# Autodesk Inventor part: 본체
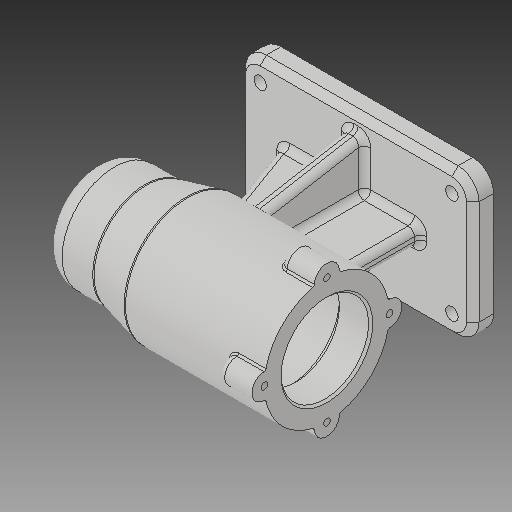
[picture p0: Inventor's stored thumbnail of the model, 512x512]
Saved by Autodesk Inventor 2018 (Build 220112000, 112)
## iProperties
Created: 2019-07
Part Number: 본체
Material: 일반
Document SubType Name: Modeling
Designer: USER
Density: 1 g/cm^3
Appearance: 기본값
Author: USER
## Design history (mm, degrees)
sketch "스케치1"
  geometry: L1 (0, 70)-(112, 70); L2 (112, 70)-(112, 0); L3 (112, 0)-(0, 0); L4 (0, 0)-(0, 70); 1 further point
  constraints: 8 end point, 2 parallel, 1 coincident, 1 horizontal, 1 perpendicular
  dimensions: "d0" = 112 distance of L1.start L1.end; "d1" = 70 distance of L3.end L1.start
extrude "돌출1" new body sketch "스케치1" distance "d2" = 10; taper "d3" = 0 deg
node "작업 평면1"
sketch "스케치2"
  geometry: L1 (0, 80)-(112, 80); L2 (112, 10)-(0, 10) reference; L3 (0, 0)-(112, 0) reference; L4 (0, 80)-(0, 105); L5 (0, 105)-(25, 105); L6 (25, 105)-(45, 110); L7 (45, 110)-(112, 110); L8 (112, 80)-(112, 110); L9 (112, 101)-(97, 101); L10 (97, 101)-(97, 104); L11 (97, 104)-(43, 104); L12 (43, 104)-(43, 101); L13 (43, 101)-(31, 101); L14 (31, 101)-(31, 97.5); L15 (31, 97.5)-(13, 97.5); L16 (13, 97.5)-(13, 96); L17 (13, 96)-(9, 96); L18 (9, 96)-(9, 90.5); L19 (9, 90.5)-(6, 90.5); L20 (6, 90.5)-(6, 80); L21 (0, 80)-(112, 80); 2 further points
  constraints: 38 end point, 11 perpendicular, 5 horizontal, 2 midpoint, 2 point on line, 2 vertical, 1 vertical alignment
  dimensions: "d4" = 112 distance of L1.start L1.end; "d5" = 80 distance between parallel lines of L3 L1; "d6" = 60 diameter of L7 L1; "d7" = 50 diameter of L5 L1; "d8" = 25 distance of L4.end L5.end; "d9" = 45 distance from line of L6.end L4; "d10" = 15 distance of L9.start L9.end; "d11" = 54 distance of L10.end L11.end; "d13" = 18 distance of L14.end L15.end; "d14" = 4 distance of L16.end L17.end; "d15" = 3 distance of L18.end L19.end; "d16" = 42 diameter of L9 L1; "d17" = 48 diameter of L11 L1; "d18" = 42 diameter of L13 L1; "d19" = 12 distance of L12.end L13.end; "d20" = 35 diameter of L15 L1; "d21" = 32 diameter of L17 L1; "d22" = 21 diameter of L19 L1
revolve "회전1" sketch "스케치2" stored, may be unused: angle "d23" = 90 deg
sketch "스케치3"
  geometry: L1 (112, 10)-(0, 10) reference; L2 (20, 10)-(36.025, 54.03); L3 (0, 0)-(0, 10) reference; L4 (87, 10)-(87, 53.035); L5 (112, 0)-(112, 10) reference; L6 (87, 53.035)-(36.025, 54.03); L7 (20, 10)-(87, 10)
  constraints: 8 end point, 2 point on line, 1 horizontal, 1 vertical
  dimensions: "d24" = 20 distance from line of L3 L2.start; "d25" = 110 deg angle of L1 L2; "d26" = 25 distance between parallel lines of L5 L4
extrude "돌출2" join sketch "스케치3" stored distance "d27" = 8; taper "d28" = 0 deg
node "작업 평면2"
sketch "스케치4"
  geometry: L1 (-10, 70)-(-10, 0) reference; L2 (-10, 7)-(-59.395, 15.71); L3 (-10, 63)-(-59.435, 54.283); L4 (0, 0)-(-10, 0) reference; L5 (0, 70)-(-10, 70) reference; L6 (-59.395, 15.71)-(-54.339, 28.739); L7 (-54.339, 28.739)-(-54.339, 46.221); L8 (-54.339, 46.221)-(-59.435, 54.283)
  constraints: 10 end point, 2 point on line, 1 vertical
  dimensions: "d29" = 7 distance from line of L2.start L4; "d30" = 7 distance from line of L3.start L5; "d31" = 100 deg angle of L2 L1; "d32" = 100 deg angle of L1 L3
extrude "돌출3" join sketch "스케치4" stored distance "d33" = 8; taper "d34" = 0 deg
sketch "스케치5"
  geometry: C1 r 6 at (-30, 0); A1 r 30 centre (0, 0) between (29.732, 4) and (29.732, -4) reference; A2 r 30 centre (0, 0) between (29.732, 4) and (29.732, -4) reference; 2 further points
  constraints: 1 centre point, 1 coincident, 1 horizontal alignment, 1 point on circle
  dimensions: "d36" = 12 diameter of C1
extrude "돌출4" join sketch "스케치5" distance "d37" = 16; taper "d38" = 0 deg
sketch "스케치6"
  geometry: C1 r 21 at (30, 0) reference; A1 r 30 centre (30, 0) between (24.03, 29.4) and (0.6, 5.97) reference; A2 r 6 centre (0, 0) between (0.6, 5.97) and (0.6, -5.97) reference; A3 r 30 centre (30, 0) between (0.6, -5.97) and (24.03, -29.4) reference; A4 r 6 centre (30, -30) between (24.03, -29.4) and (35.97, -29.4) reference; A5 r 30 centre (30, 0) between (35.97, -29.4) and (59.4, -5.97) reference; A6 r 6 centre (60, 0) between (59.4, -5.97) and (59.4, 5.97) reference; A7 r 30 centre (30, 0) between (59.4, 5.97) and (35.97, 29.4) reference; A8 r 6 centre (30, 30) between (35.97, 29.4) and (24.03, 29.4) reference; 2 further points
  constraints: 1 coincident
hole "구멍1" sketch "스케치6" at (0, 0) diameter "d42" = 3.242; stored, may be unused: countersink angle "d46" = 90 deg, drill point angle "d48" = 118 deg; dims "d43" = 8, "d44" = 4, "d45" = 2, "d47" = 11
sketch "스케치7"
  geometry: L1 (0, 0)-(0, 70) reference; L2 (0, 70)-(112, 70) reference; L3 (112, 0)-(0, 0) reference; L4 (112, 70)-(112, 0) reference; C1 r 3 at (10, 60); C2 r 3 at (102, 60); C3 r 3 at (102, 10); C4 r 3 at (10, 10)
  constraints: 4 centre point
  dimensions: "d52" = 10 distance from line of C1.centre L1; "d53" = 10 distance from line of C1.centre L2; "d54" = 10 distance from line of L1 C4.centre; "d55" = 10 distance from line of C4.centre L3; "d56" = 10 distance from line of C2.centre L2; "d57" = 10 distance from line of C2.centre L4; "d58" = 10 distance from line of C3.centre L4; "d59" = 10 distance from line of C3.centre L3; "d60" = 6 diameter of C1; "d61" = 6 diameter of C4; "d62" = 6 diameter of C3; "d63" = 6 diameter of C2
extrude "돌출5" cut sketch "스케치7" distance "d64" = 16; taper "d65" = 0 deg
fillet "모깎기1" dims "d66" = 10
fillet "모깎기3" dims "d68" = 10
fillet "모깎기4" dims "d69" = 3
fillet "모깎기5" dims "d70" = 3
fillet "모깎기6" dims "d71" = 3
fillet "모깎기7" dims "d72" = 1
chamfer "모따기1" distance "d73" = 3; stored, may be unused: second distance "d74" = 2, angle "d75" = 45 deg
fillet "모깎기8" dims "d76" = 3
fillet "모깎기9" dims "d77" = 0.3
fillet "모깎기10" dims "d78" = 3
fillet "모깎기11" dims "d79" = 3
chamfer "모따기2" distance "d80" = 1; stored, may be unused: second distance "d81" = 2, angle "d82" = 45 deg
node "솔리드1"
pattern_circular "원형 패턴1" dims angle "d40" = 360 deg
pattern_circular "원형 패턴2" dims angle "d50" = 360 deg
node "투영된 루프1"
